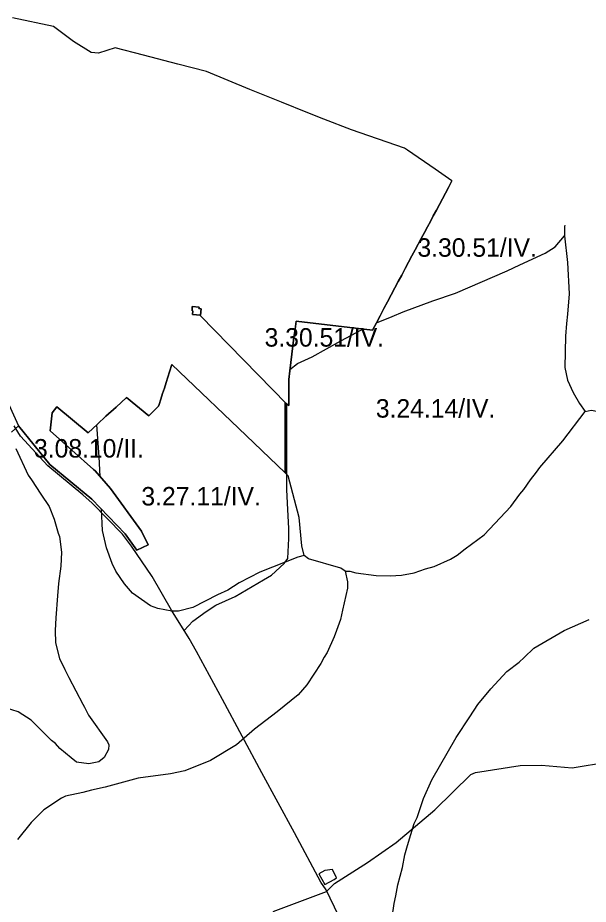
# Model space of a CAD drawing. Extents: x -555509 to -553014, y -1186753 to -1182560.
# Drawn here: x -554556 to -553938, y -1183564 to -1182605 of the extents above; entities that cross this region are included whole.
import ezdxf

# ---------------------------------------------------------------- set-up
doc = ezdxf.new("R2010")
doc.units = 0
for name, color, linetype in [('Level 29', 7, 'Continuous'), ('Level 52', 7, 'Continuous'), ('pěší_tr', 7, 'Continuous'), ('ZM2_KOO_legenda', 7, 'Continuous')]:
    doc.layers.add(name, color=color, linetype=linetype)

msp = doc.modelspace()

# ---------------------------------------------------------------- linework, layer by layer
at = {"layer": 'Level 29'}
for points in [[(-554085.58, -1182781.01), (-554089.43, -1182788.23), (-554092.75, -1182794.46), (-554095.99, -1182800.56), (-554099.16, -1182806.51), (-554102.5, -1182812.78), (-554105.78, -1182818.94), (-554108.98, -1182824.94), (-554112.18, -1182830.94), (-554115.38, -1182836.94), (-554118.76, -1182843.3), (-554122.11, -1182849.59), (-554125.47, -1182855.88), (-554128.92, -1182862.36), (-554132.55, -1182869.18), (-554136.23, -1182876.09), (-554139.94, -1182883.05), (-554143.66, -1182890.03), (-554147.38, -1182897.03), (-554151.42, -1182904.61), (-554155.33, -1182911.94), (-554159.3, -1182919.39), (-554163.4, -1182927.1), (-554167.47, -1182934.74), (-554171.63, -1182942.54), (-554254.38, -1182933.03), (-554255.52, -1182941.75), (-554256.73, -1182950.69), (-554257.85, -1182959.52), (-554258.99, -1182968.54), (-554260.14, -1182977.6), (-554261.3, -1182986.71), (-554262.22, -1182995.89), (-554262.21, -1183005.1), (-554262.33, -1183014.59), (-554262.38, -1183024.08), (-554266.38, -1183021.27), (-554266.32, -1183061.49), (-554266.18, -1183097.12), (-554316.77, -1183048.71), (-554372.68, -1182995.2), (-554388.93, -1182979.65), (-554391.47, -1182987.64), (-554393.27, -1182993.57), (-554395.17, -1182999.46), (-554397, -1183005.38), (-554398.87, -1183011.31), (-554400.71, -1183017.23), (-554402.67, -1183023.1), (-554403.33, -1183025.09), (-554413.98, -1183035.48), (-554437.96, -1183015.71), (-554449.17, -1183025.95), (-554460.24, -1183035.89), (-554469.42, -1183044.22), (-554479.62, -1183053.63), (-554513.4, -1183025.76), (-554518.6, -1183032.04), (-554519.39, -1183038.52), (-554520.07, -1183045.01), (-554520.76, -1183051.66), (-554473.59, -1183093.62), (-554472.09, -1183094.95), (-554455.4, -1183113.91), (-554421.72, -1183160.34), (-554414.65, -1183175.07), (-554426.66, -1183180.83), (-554439.49, -1183162.97), (-554475.52, -1183125.71), (-554520.97, -1183088.05)], [(-553963.35, -1182828.9), (-553963.75, -1182830.5), (-553963.75, -1182834.77), (-553963.75, -1182837.49), (-553963.75, -1182838.57), (-553963.75, -1182840.62)], [(-554167.42, -1182934.65), (-554150.31, -1182928), (-554138.44, -1182922.88), (-554106.19, -1182911), (-554081.62, -1182902.5), (-554025.69, -1182878.38), (-554012.12, -1182872), (-553984.56, -1182859.25), (-553973.94, -1182852.5), (-553963.75, -1182840.62)], [(-553963.75, -1182840.62), (-553960.38, -1182869.5), (-553958.69, -1182903.38), (-553960.38, -1182925.5), (-553961.62, -1182935.63), (-553962.5, -1182949.12), (-553963.31, -1182983.12), (-553960.38, -1182996.63), (-553954.44, -1183010.25), (-553947.62, -1183022.12), (-553941.31, -1183030.62)], [(-554261.13, -1182985.33), (-554252.94, -1182978.88), (-554236.81, -1182971.63), (-554205.88, -1182954.25), (-554183.38, -1182942.38), (-554181.4, -1182941.42)], [(-554201.19, -1183203.63), (-554196.12, -1183203.63), (-554189.75, -1183205.25), (-554167.69, -1183208.25), (-554152.44, -1183208.62), (-554140.12, -1183207.75), (-554126.56, -1183205.25), (-554114.25, -1183201), (-554104.94, -1183198.5), (-554087.12, -1183190.38), (-554079.94, -1183186.25), (-554071.44, -1183179.38), (-554050.69, -1183164.12), (-554021.88, -1183133.63), (-554012.12, -1183120), (-554007.88, -1183115), (-554000.62, -1183104.75), (-553993.88, -1183096.25), (-553990.5, -1183091.25), (-553965.44, -1183062.38), (-553941.31, -1183030.62)], [(-553941.31, -1183030.62), (-553934.94, -1183029.38), (-553908.25, -1183034), (-553891.25, -1183039.12), (-553856.94, -1183052.25), (-553845.88, -1183063.62)], [(-554520.97, -1183088.05), (-554554.89, -1183046.35), (-554562.53, -1183053.13)], [(-554466.55, -1183101.2), (-554467.44, -1183079.75), (-554470.31, -1183045.04)], [(-554557.75, -1183070.88), (-554544.62, -1183099.75), (-554540.81, -1183104.75), (-554530.62, -1183120), (-554521.69, -1183133.63), (-554516.19, -1183147.13), (-554511.94, -1183162.5), (-554510.69, -1183165.88), (-554508.56, -1183182.75), (-554509, -1183198), (-554511.56, -1183216.75), (-554512.81, -1183230.25), (-554514.5, -1183254), (-554515.38, -1183267.63), (-554514.94, -1183281.12), (-554510.69, -1183298.12), (-554504.75, -1183310), (-554500.5, -1183318.5), (-554485.25, -1183347.25), (-554483.56, -1183350.75), (-554479.31, -1183359.12), (-554458.56, -1183388), (-554457.25, -1183391.38), (-554457.69, -1183396.5), (-554462.38, -1183405), (-554467.88, -1183409.63), (-554478.88, -1183412.12), (-554492.06, -1183410), (-554498, -1183405.38), (-554510.25, -1183395.25), (-554514.94, -1183390.13), (-554519.19, -1183386.75), (-554541.19, -1183364.63), (-554555.19, -1183355.75), (-554569.19, -1183351.5)], [(-554245.71, -1183186.6), (-554248.25, -1183176), (-554251.19, -1183145.5), (-554262.81, -1183100.35), (-554266.18, -1183097.12)], [(-554245.71, -1183186.6), (-554252.5, -1183188.25), (-554293.62, -1183204.38), (-554316.06, -1183216.25), (-554328.38, -1183223.88), (-554339.38, -1183229), (-554366.12, -1183242.63), (-554381.81, -1183246.88), (-554389, -1183246.88), (-554404.25, -1183243.88), (-554411.88, -1183240.88), (-554431.38, -1183227.25), (-554440.31, -1183217.12), (-554449.62, -1183203.63), (-554453.44, -1183195.13), (-554459.81, -1183178.13), (-554464.06, -1183159.5), (-554465.06, -1183136.53)], [(-554201.19, -1183203.63), (-554205.88, -1183200.12), (-554241.06, -1183190), (-554245.71, -1183186.6)], [(-554201.19, -1183203.63), (-554198.62, -1183215), (-554198.62, -1183221.75), (-554204.12, -1183245.5), (-554206.25, -1183255.75), (-554210.5, -1183267.63), (-554213.06, -1183274.38), (-554220.69, -1183291.38), (-554224.06, -1183296.38), (-554227.5, -1183303.25), (-554242.75, -1183326.5), (-554252.06, -1183337.13), (-554274.94, -1183355.75), (-554299.56, -1183374.38), (-554319.06, -1183391.38), (-554347.06, -1183408.38), (-554375, -1183419.38), (-554390.25, -1183422.75), (-554425.5, -1183427.38), (-554461.06, -1183437.13), (-554475.94, -1183440.62), (-554485.25, -1183443.12), (-554503.94, -1183446.88), (-554508.56, -1183449), (-554527.62, -1183461.75), (-554541.19, -1183475.38), (-554556.06, -1183494)], [(-554133.75, -1183500.38), (-554126.56, -1183476.62), (-554123.19, -1183469.88), (-554116.38, -1183449.5), (-554107.5, -1183429.13), (-554081.19, -1183383.38), (-554066.38, -1183361.25), (-554057.44, -1183347.75), (-554043.5, -1183330.75), (-554026.06, -1183312.13), (-554012.94, -1183301.88), (-554007.44, -1183296.88), (-553996.81, -1183286.62), (-553964.19, -1183267.63), (-553937.06, -1183255.75)], [(-554152, -1183590.25), (-554148.19, -1183563.13), (-554146.5, -1183554.63), (-554144.38, -1183542.75), (-554139.31, -1183524.12), (-554136.75, -1183510.5), (-554133.75, -1183500.38)]]:
    msp.add_lwpolyline(points, dxfattribs=at)
at = {"layer": 'Level 52'}
for points in [[(-554359.68, -1182919.31), (-554359.46, -1182917.77), (-554366.75, -1182917.09), (-554367.01, -1182921.82), (-554366.06, -1182921.91), (-554366.42, -1182925.69), (-554357.96, -1182926.5), (-554357.31, -1182919.65), (-554359.68, -1182919.31)], [(-554223.21, -1183527.27), (-554229.62, -1183530.91), (-554223.28, -1183542.57), (-554213.17, -1183536.99), (-554210.64, -1183535.29), (-554214.97, -1183526.21), (-554223.21, -1183527.27)]]:
    msp.add_lwpolyline(points, dxfattribs=at)
at = {"layer": 'pěší_tr'}
for points in [[(-554264.27, -1183023.98), (-554264.28, -1183022.64), (-554358.26, -1182926.87)], [(-554375.46, -1183267.83), (-554366.01, -1183257.71), (-554351.76, -1183247.16), (-554341.14, -1183240.17), (-554320.18, -1183230.99), (-554289.69, -1183212.76), (-554281.06, -1183207.69), (-554267.36, -1183195.09), (-554263.38, -1183189.81), (-554262.15, -1183167.96), (-554262.08, -1183157.13), (-554263.45, -1183136.85), (-554264.27, -1183115.61), (-554264.48, -1183097.13), (-554264.27, -1183023.98)], [(-554208.57, -1183575.94), (-554221.86, -1183548.4), (-554227.48, -1183540.18), (-554256.11, -1183486.74), (-554291.33, -1183421.65), (-554333.94, -1183342.18), (-554362.38, -1183290.42), (-554369.98, -1183276.51), (-554389.44, -1183245.68), (-554410.27, -1183209.3), (-554432.74, -1183176.35), (-554442.33, -1183163.33), (-554475.15, -1183129.83), (-554485.22, -1183120.75), (-554523.17, -1183089.37), (-554552.63, -1183057.31), (-554559.76, -1183046.21)], [(-554279.12, -1183571.77), (-554221.57, -1183550.12), (-554212.8, -1183541.35), (-554177.18, -1183518.6), (-554146.07, -1183496.96), (-554104.15, -1183461.6), (-554065.1, -1183423.51), (-554060.16, -1183421.32), (-554011.66, -1183413.64), (-553988.78, -1183413.37), (-553955.48, -1183416.39), (-553916.02, -1183409.67)]]:
    msp.add_lwpolyline(points, dxfattribs=at)
at = {"layer": 'ZM2_KOO_legenda'}
for p, q in [((-554517.15, -1182614.23), (-554561.36, -1182604.56)), ((-554495.48, -1182630.28), (-554517.15, -1182614.23)), ((-554476.43, -1182642.32), (-554495.48, -1182630.28)), ((-554468.32, -1182642.79), (-554476.43, -1182642.32)), ((-554450.19, -1182636.98), (-554468.32, -1182642.79)), ((-554419.74, -1182644.94), (-554450.19, -1182636.98)), ((-554382.27, -1182654.75), (-554419.74, -1182644.94)), ((-554351.46, -1182662.7), (-554382.27, -1182654.75)), ((-554304.41, -1182682.05), (-554351.46, -1182662.7)), ((-554270.07, -1182696.11), (-554304.41, -1182682.05)), ((-554260.59, -1182699.84), (-554270.07, -1182696.11)), ((-554257.43, -1182701.08), (-554260.59, -1182699.84)), ((-554254.15, -1182702.37), (-554257.43, -1182701.08)), ((-554224.4, -1182714.16), (-554254.15, -1182702.37)), ((-554194.54, -1182725.99), (-554224.4, -1182714.16)), ((-554136.89, -1182745.57), (-554194.54, -1182725.99)), ((-554133.74, -1182747.74), (-554136.89, -1182745.57)), ((-554103.65, -1182768.52), (-554133.74, -1182747.74)), ((-554085.58, -1182781.01), (-554103.65, -1182768.52)), ((-554092.75, -1182794.46), (-554089.43, -1182788.23)), ((-554089.43, -1182788.23), (-554085.58, -1182781.01)), ((-554095.99, -1182800.56), (-554092.75, -1182794.46)), ((-554102.5, -1182812.78), (-554099.16, -1182806.51)), ((-554099.16, -1182806.51), (-554095.99, -1182800.56)), ((-554105.78, -1182818.94), (-554102.5, -1182812.78)), ((-554112.18, -1182830.94), (-554108.98, -1182824.94)), ((-554108.98, -1182824.94), (-554105.78, -1182818.94)), ((-554118.76, -1182843.3), (-554115.38, -1182836.94)), ((-554115.38, -1182836.94), (-554112.18, -1182830.94)), ((-554122.11, -1182849.59), (-554118.76, -1182843.3)), ((-554128.92, -1182862.36), (-554125.47, -1182855.88)), ((-554125.47, -1182855.88), (-554122.11, -1182849.59)), ((-554132.55, -1182869.18), (-554128.92, -1182862.36)), ((-554136.23, -1182876.09), (-554132.55, -1182869.18)), ((-554143.66, -1182890.03), (-554139.94, -1182883.05)), ((-554139.94, -1182883.05), (-554136.23, -1182876.09)), ((-554147.38, -1182897.03), (-554143.66, -1182890.03)), ((-554151.42, -1182904.61), (-554147.38, -1182897.03)), ((-554159.3, -1182919.39), (-554155.33, -1182911.94)), ((-554155.33, -1182911.94), (-554151.42, -1182904.61)), ((-554367.01, -1182921.82), (-554366.75, -1182917.09)), ((-554366.06, -1182921.91), (-554367.01, -1182921.82)), ((-554366.75, -1182917.09), (-554359.46, -1182917.77)), ((-554366.42, -1182925.69), (-554366.06, -1182921.91)), ((-554359.46, -1182917.77), (-554359.68, -1182919.31)), ((-554359.68, -1182919.31), (-554357.31, -1182919.65)), ((-554357.31, -1182919.65), (-554357.96, -1182926.5)), ((-554163.4, -1182927.1), (-554159.3, -1182919.39)), ((-554357.96, -1182926.5), (-554366.42, -1182925.69)), ((-554167.47, -1182934.74), (-554163.4, -1182927.1)), ((-554256.73, -1182950.69), (-554255.52, -1182941.75)), ((-554255.52, -1182941.75), (-554254.38, -1182933.03)), ((-554254.38, -1182933.03), (-554171.63, -1182942.54)), ((-554171.63, -1182942.54), (-554167.47, -1182934.74)), ((-554257.85, -1182959.52), (-554256.73, -1182950.69)), ((-554258.99, -1182968.54), (-554257.85, -1182959.52)), ((-554260.14, -1182977.6), (-554258.99, -1182968.54)), ((-554391.47, -1182987.64), (-554388.93, -1182979.65)), ((-554388.93, -1182979.65), (-554372.68, -1182995.2)), ((-554261.3, -1182986.71), (-554260.14, -1182977.6)), ((-554393.27, -1182993.57), (-554391.47, -1182987.64)), ((-554262.22, -1182995.89), (-554261.3, -1182986.71)), ((-554397, -1183005.38), (-554395.17, -1182999.46)), ((-554395.17, -1182999.46), (-554393.27, -1182993.57)), ((-554372.68, -1182995.2), (-554316.77, -1183048.71)), ((-554262.21, -1183005.1), (-554262.22, -1182995.89)), ((-554398.87, -1183011.31), (-554397, -1183005.38)), ((-554262.33, -1183014.59), (-554262.21, -1183005.1)), ((-554570.74, -1183011.26), (-554554.89, -1183046.35)), ((-554449.17, -1183025.95), (-554437.96, -1183015.71)), ((-554437.96, -1183015.71), (-554413.98, -1183035.48)), ((-554402.67, -1183023.1), (-554400.71, -1183017.23)), ((-554400.71, -1183017.23), (-554398.87, -1183011.31)), ((-554262.38, -1183024.08), (-554262.33, -1183014.59)), ((-554518.6, -1183032.04), (-554513.4, -1183025.76)), ((-554513.4, -1183025.76), (-554479.62, -1183053.63)), ((-554460.24, -1183035.89), (-554449.17, -1183025.95)), ((-554413.98, -1183035.48), (-554403.33, -1183025.09)), ((-554403.33, -1183025.09), (-554402.67, -1183023.1)), ((-554266.32, -1183061.49), (-554266.38, -1183021.27)), ((-554266.38, -1183021.27), (-554262.38, -1183024.08)), ((-554519.39, -1183038.52), (-554518.6, -1183032.04)), ((-554469.42, -1183044.22), (-554460.24, -1183035.89)), ((-554554.89, -1183046.35), (-554520.97, -1183088.05)), ((-554520.76, -1183051.66), (-554520.07, -1183045.01)), ((-554520.07, -1183045.01), (-554519.39, -1183038.52)), ((-554479.62, -1183053.63), (-554469.42, -1183044.22)), ((-554473.59, -1183093.62), (-554520.76, -1183051.66)), ((-554316.77, -1183048.71), (-554266.18, -1183097.12)), ((-554266.18, -1183097.12), (-554266.32, -1183061.49)), ((-554520.97, -1183088.05), (-554475.52, -1183125.71)), ((-554472.09, -1183094.95), (-554473.59, -1183093.62)), ((-554455.4, -1183113.91), (-554472.09, -1183094.95)), ((-554421.72, -1183160.34), (-554455.4, -1183113.91)), ((-554475.52, -1183125.71), (-554439.49, -1183162.97)), ((-554439.49, -1183162.97), (-554426.66, -1183180.83)), ((-554414.65, -1183175.07), (-554421.72, -1183160.34)), ((-554426.66, -1183180.83), (-554414.65, -1183175.07))]:
    msp.add_line(p, q, dxfattribs=at)

# ---------------------------------------------------------------- texts
at = {"layer": 'Level 29'}
for s, p in [('3.30.51/IV.', (-554122.96, -1182863.23)), ('3.30.51/IV.', (-554288.47, -1182960.48)), ('3.24.14/IV.', (-554168.02, -1183037.31)), ('3.08.10/II.', (-554538.17, -1183080.52)), ('3.27.11/IV.', (-554421.89, -1183132.39))]:
    msp.add_text(s, height=20, dxfattribs=at).set_placement(p)

doc.saveas('drawing.dxf')
